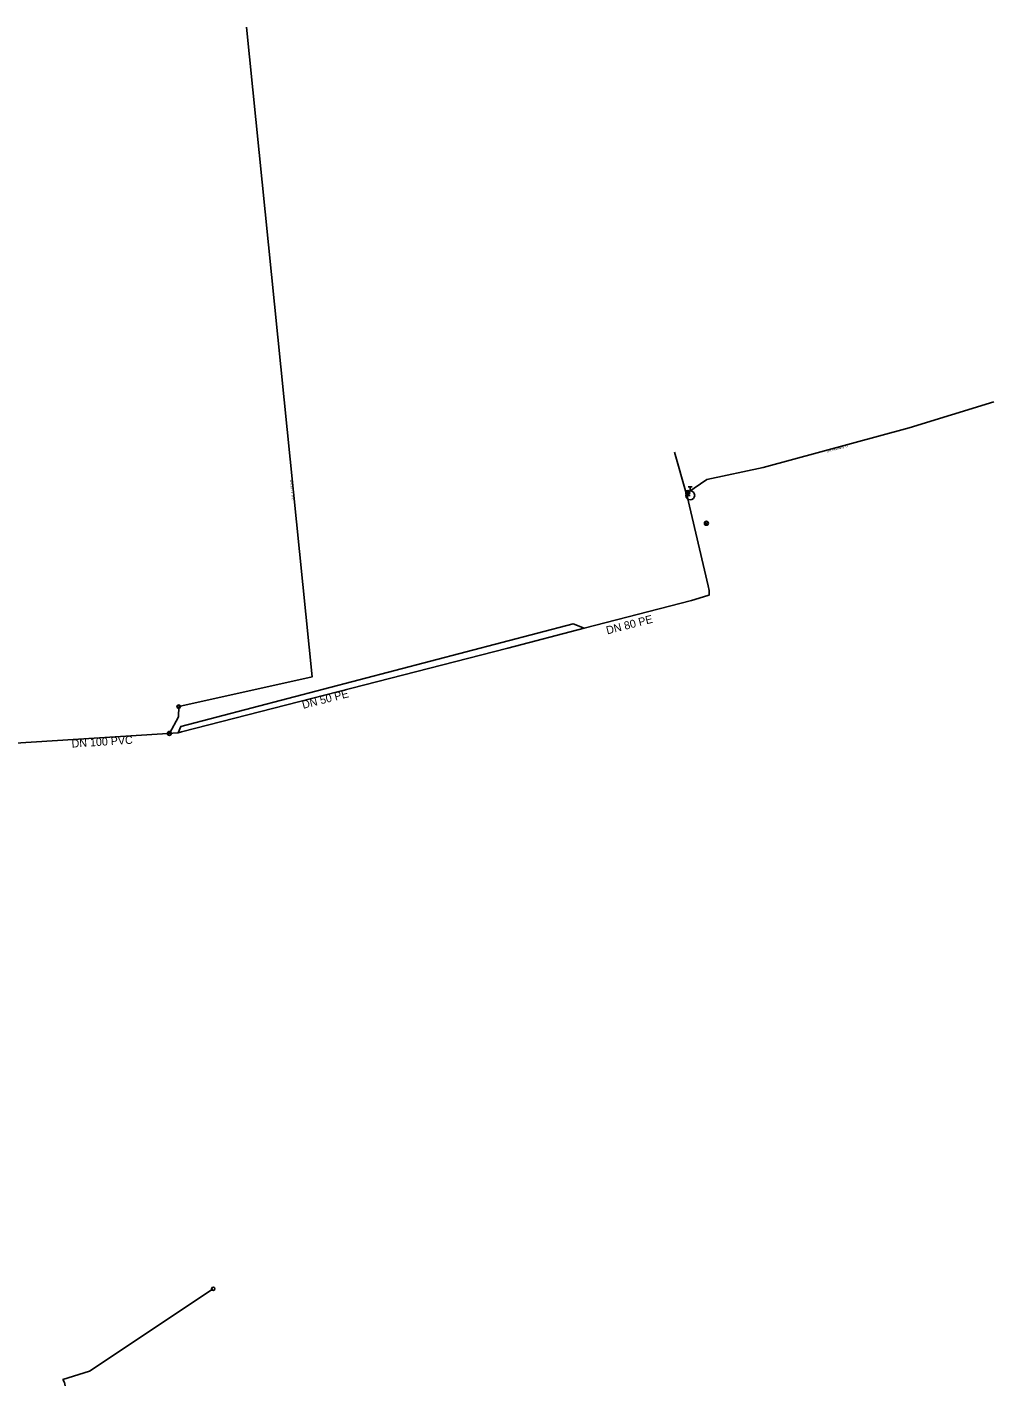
# Model space of a CAD drawing. Extents: x -452548 to -451108, y -1100145 to -1099658.
# Drawn here: x -451735.5 to -451541.6, y -1099976.4 to -1099703.9 of the extents above; entities that cross this region are included whole.
import ezdxf

# ---------------------------------------------------------------- set-up
doc = ezdxf.new("R2010")
doc.units = 0
for name, color, linetype in [('_hydrantova_odbocka_', 7, 'Continuous'), ('_pripojka_prevzato_z_dokumentace_', 7, 'Continuous'), ('_pripojka_priblizne_', 7, 'Continuous'), ('_voda_projekt_smvak_', 7, 'Continuous'), ('_voda_smvak_prevzato_z_dokumentace_', 7, 'Continuous'), ('Default', 7, 'Continuous'), ('MoLevel 28', 7, 'Continuous'), ('MoLevel 30', 7, 'Continuous'), ('MoLevel 32', 7, 'Continuous'), ('MoLevel 46', 7, 'Continuous'), ('MoLevel 53', 7, 'Continuous'), ('MoLevel 55', 7, 'Continuous')]:
    doc.layers.add(name, color=color, linetype=linetype)

# ---------------------------------------------------------------- blocks, each defined once
blk = doc.blocks.new('_uzaver_pripojka_')
at = {"layer": 'Default'}
for p, q in [((-0.000035, -0.000035), (0.000035, 0.000035)), ((0.000035, -0.000035), (-0.000035, 0.000035))]:
    blk.add_line(p, q, dxfattribs=at)
for radius in [0.00005, 0.0000025]:
    blk.add_circle((0, 0), radius, dxfattribs=at)
blk = doc.blocks.new('_hydrant_voda_')
at = {"layer": 'Default'}
for p, q in [((-0.000023, 0.000095), (0.000023, 0.000095)), ((0, 0.000095), (0, 0.00005))]:
    blk.add_line(p, q, dxfattribs=at)
blk.add_circle((0, 0), 0.00005, dxfattribs=at)
blk = doc.blocks.new('_sachta_voda_')
at = {"layer": 'Default'}
blk.add_circle((0, 0), 0.000035, dxfattribs=at)

msp = doc.modelspace()

# ---------------------------------------------------------------- linework, layer by layer
at = {"layer": '_hydrantova_odbocka_'}
msp.add_line((-451603.08, -1099797.97), (-451602.45, -1099797.79), dxfattribs=at)
at = {"layer": '_pripojka_prevzato_z_dokumentace_'}
for points in [[(-451603.26, -1099797.32), (-451602.97, -1099797.24), (-451599.14, -1099794.64), (-451587.82, -1099792.2), (-451558.56, -1099784.27), (-451541.56, -1099779.01)], [(-451706.94, -1099845.55), (-451705.11, -1099842.23), (-451705.06, -1099840.17)]]:
    msp.add_lwpolyline(points, dxfattribs=at)
at = {"layer": '_pripojka_priblizne_'}
for points in [[(-451705.06, -1099840.17), (-451678.32, -1099834.21), (-451691.46, -1099703.89)], [(-451727.87, -1099976.39), (-451727.95, -1099975.72), (-451728.3, -1099975.14), (-451722.97, -1099973.45), (-451698.14, -1099956.93)]]:
    msp.add_lwpolyline(points, dxfattribs=at)
at = {"layer": '_voda_projekt_smvak_'}
msp.add_lwpolyline([(-451705.18, -1099845.42), (-451704.67, -1099844.12), (-451625.97, -1099823.56), (-451623.75, -1099824.44)], dxfattribs=at)
at = {"layer": '_voda_smvak_prevzato_z_dokumentace_'}
for points in [[(-451598.92, -1099817.89), (-451598.64, -1099817.8), (-451598.67, -1099816.87), (-451598.88, -1099815.92), (-451603.08, -1099797.97), (-451603.26, -1099797.32), (-451605.6, -1099789.12)], [(-451623.75, -1099824.44), (-451602.18, -1099818.86), (-451598.92, -1099817.89)], [(-451704.49, -1099845.24), (-451639.06, -1099828.42), (-451623.75, -1099824.44)], [(-451779.64, -1099843.93), (-451779.43, -1099844.82), (-451774.74, -1099849.86), (-451705.18, -1099845.42), (-451704.49, -1099845.24)]]:
    msp.add_lwpolyline(points, dxfattribs=at)

# ---------------------------------------------------------------- block references
at = {"layer": 'MoLevel 28', "xscale": 17636.68430335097, "yscale": 17636.68430335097}
msp.add_blockref('_hydrant_voda_', (-451602.45, -1099797.79), dxfattribs=at)
at = {"layer": 'MoLevel 30', "xscale": 10000, "yscale": 10000}
for p in [(-451705.06, -1099840.17), (-451698.14, -1099956.93)]:
    msp.add_blockref('_sachta_voda_', p, dxfattribs=at)
at = {"layer": 'MoLevel 53', "xscale": 7999.999999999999, "yscale": 7999.999999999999}
for p in [(-451602.97, -1099797.24), (-451599.22, -1099803.39), (-451706.94, -1099845.55)]:
    msp.add_blockref('_uzaver_pripojka_', p, dxfattribs=at)

# ---------------------------------------------------------------- texts
at = {"layer": 'MoLevel 32'}
msp.add_text("DN 50 - 2'' IPE", height=0.455, rotation=275.7591, dxfattribs=at).set_placement((-451682.76, -1099794.73))
at = {"layer": 'MoLevel 46'}
for s, rotation, p in [('DN 80 PE', 14.5131, (-451619.09, -1099825.69)), ('DN 50 PE', 14.4151, (-451680.09, -1099840.62)), ('DN 100 PVC', 3.6581, (-451726.5, -1099848.39))]:
    msp.add_text(s, height=1.605, rotation=rotation, dxfattribs=at).set_placement(p)
at = {"layer": 'MoLevel 55'}
msp.add_text('DN neznámý O', height=0.455, rotation=15.1639, dxfattribs=at).set_placement((-451574.99, -1099789.19))

doc.saveas('drawing.dxf')
